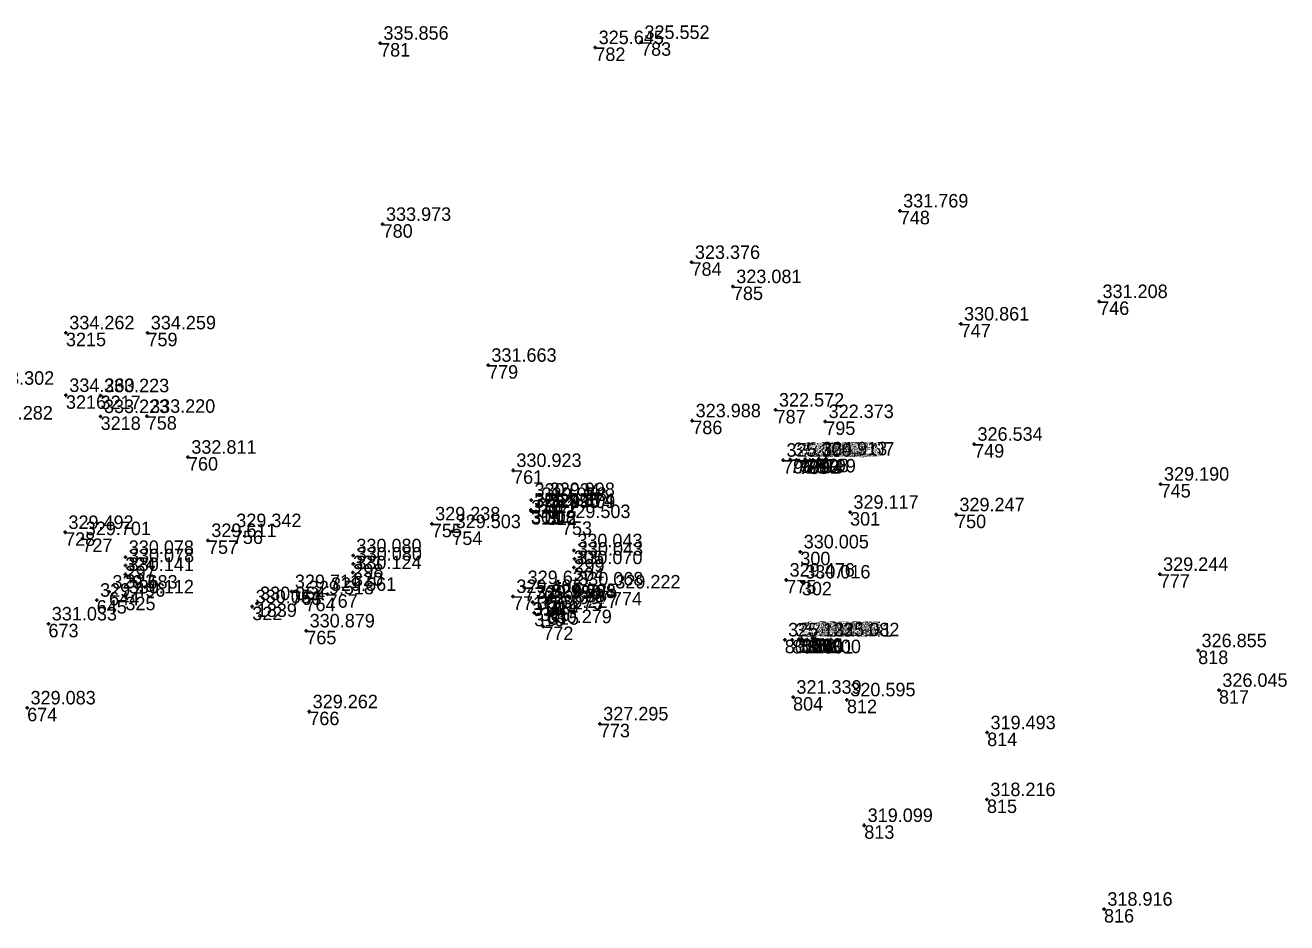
# Model space of a CAD drawing. Extents: x -829398 to -819400, y -1074439 to -1067977.
# Drawn here: x -824511.5 to -824399.2, y -1072412.8 to -1072332.9 of the extents above; entities that cross this region are included whole.
import ezdxf

# ---------------------------------------------------------------- set-up
doc = ezdxf.new("R2010")
doc.units = 0
for name, color, linetype in [('Vrstva 60', 7, 'Continuous'), ('Vrstva 61', 7, 'Continuous'), ('Čísla bodů_doměření_2012', 7, 'Continuous')]:
    doc.layers.add(name, color=color, linetype=linetype)

# ---------------------------------------------------------------- blocks, each defined once
blk = doc.blocks.new('BOD')
at = {"layer": 'Čísla bodů_doměření_2012'}
for p, q in [((-0.15, 0), (0.15, 0)), ((0, -0.15), (0, 0.15))]:
    blk.add_line(p, q, dxfattribs=at)

msp = doc.modelspace()

# ---------------------------------------------------------------- block references
at = {"layer": 'Vrstva 60'}
for p in [(-824479.933, -1072334.535), (-824460.777, -1072334.929), (-824456.704, -1072334.466), (-824433.677, -1072349.465), (-824479.706, -1072350.656), (-824452.213, -1072354.044), (-824448.53, -1072356.201), (-824415.935, -1072357.526), (-824428.259, -1072359.525), (-824507.891, -1072360.309), (-824500.638, -1072360.312), (-824470.324, -1072363.198), (-824507.89, -1072365.882), (-824504.805, -1072365.91), (-824444.732, -1072367.184), (-824504.805, -1072367.759), (-824500.702, -1072367.738), (-824452.146, -1072368.139), (-824440.312, -1072368.207), (-824427.062, -1072370.226), (-824497.031, -1072371.379), (-824444.066, -1072371.646), (-824443.438, -1072371.592), (-824442.883, -1072371.636), (-824442.653, -1072371.678), (-824442.638, -1072371.684), (-824442.107, -1072371.567), (-824441.669, -1072371.645), (-824441.659, -1072371.656), (-824441.409, -1072371.617), (-824440.889, -1072371.523), (-824440.262, -1072371.546), (-824468.099, -1072372.558), (-824410.462, -1072373.776), (-824466.482, -1072375.207), (-824465.136, -1072375.148), (-824466.507, -1072376.083), (-824466.498, -1072376.184), (-824465.863, -1072375.576), (-824465.195, -1072376.114), (-824465.101, -1072376.213), (-824438.103, -1072376.276), (-824475.329, -1072377.309), (-824463.747, -1072377.104), (-824428.669, -1072376.503), (-824507.969, -1072378.075), (-824506.428, -1072378.624), (-824493.032, -1072377.913), (-824473.506, -1072378.001), (-824495.251, -1072378.792), (-824462.677, -1072379.7), (-824442.53, -1072379.802), (-824502.6, -1072380.298), (-824482.34, -1072380.149), (-824482.313, -1072380.883), (-824462.627, -1072380.442), (-824502.605, -1072381.813), (-824502.582, -1072381.033), (-824482.346, -1072381.653), (-824462.676, -1072381.208), (-824410.543, -1072381.804), (-824467.1, -1072382.981), (-824462.599, -1072383.105), (-824443.784, -1072382.317), (-824442.393, -1072382.481), (-824505.152, -1072384.106), (-824504.055, -1072383.382), (-824502.6, -1072383.811), (-824487.815, -1072383.339), (-824486.576, -1072383.891), (-824484.601, -1072383.584), (-824468.103, -1072383.773), (-824466.368, -1072384.28), (-824466.343, -1072384.304), (-824465.049, -1072384.228), (-824464.946, -1072384.143), (-824459.297, -1072383.372), (-824491.304, -1072384.69), (-824490.91, -1072384.405), (-824466.21, -1072385.238), (-824465.679, -1072384.76), (-824464.906, -1072385.096), (-824509.449, -1072386.217), (-824465.408, -1072386.458), (-824486.5, -1072386.835), (-824443.919, -1072387.635), (-824443.263, -1072387.652), (-824442.667, -1072387.591), (-824442.421, -1072387.534), (-824442.418, -1072387.577), (-824441.908, -1072387.625), (-824441.445, -1072387.5), (-824441.418, -1072387.535), (-824441.201, -1072387.519), (-824440.486, -1072387.658), (-824439.815, -1072387.626), (-824407.119, -1072388.598), (-824405.269, -1072392.124), (-824443.177, -1072392.737), (-824438.38, -1072392.968), (-824511.342, -1072393.689), (-824486.232, -1072394.034), (-824460.371, -1072395.116), (-824425.902, -1072395.9), (-824425.919, -1072401.852), (-824436.836, -1072404.15), (-824415.502, -1072411.603)]:
    msp.add_blockref('BOD', p, dxfattribs=at)

# ---------------------------------------------------------------- texts
for s, p in [('781', (-824479.933, -1072335.735)), ('783', (-824456.704, -1072335.666)), ('782', (-824460.777, -1072336.129)), ('748', (-824433.677, -1072350.665)), ('780', (-824479.706, -1072351.856)), ('784', (-824452.213, -1072355.244)), ('785', (-824448.53, -1072357.401)), ('746', (-824415.935, -1072358.726)), ('3215', (-824507.891, -1072361.509)), ('759', (-824500.638, -1072361.512)), ('747', (-824428.259, -1072360.725)), ('779', (-824470.324, -1072364.398)), ('3216', (-824507.89, -1072367.082)), ('3217', (-824504.805, -1072367.11)), ('787', (-824444.732, -1072368.384)), ('3218', (-824504.805, -1072368.959)), ('758', (-824500.702, -1072368.938)), ('786', (-824452.146, -1072369.339)), ('795', (-824440.312, -1072369.407)), ('749', (-824427.062, -1072371.426)), ('760', (-824497.031, -1072372.579)), ('796', (-824444.066, -1072372.846)), ('797', (-824443.438, -1072372.792)), ('788', (-824442.883, -1072372.836)), ('790', (-824442.653, -1072372.878)), ('789', (-824442.638, -1072372.884)), ('791', (-824442.107, -1072372.767)), ('792', (-824441.669, -1072372.845)), ('793', (-824441.659, -1072372.856)), ('794', (-824441.409, -1072372.817)), ('798', (-824440.889, -1072372.723)), ('799', (-824440.262, -1072372.746)), ('761', (-824468.099, -1072373.758)), ('745', (-824410.462, -1072374.976)), ('310', (-824466.482, -1072376.407)), ('311', (-824465.136, -1072376.348)), ('309', (-824466.507, -1072377.283)), ('313', (-824466.498, -1072377.384)), ('307', (-824465.863, -1072376.776)), ('308', (-824465.195, -1072377.314)), ('312', (-824465.101, -1072377.413)), ('301', (-824438.103, -1072377.476)), ('755', (-824475.329, -1072378.509)), ('753', (-824463.747, -1072378.304)), ('750', (-824428.669, -1072377.703)), ('728', (-824507.969, -1072379.275)), ('756', (-824493.032, -1072379.113)), ('754', (-824473.506, -1072379.201)), ('727', (-824506.428, -1072379.824)), ('757', (-824495.251, -1072379.992)), ('305', (-824462.677, -1072380.9)), ('324', (-824502.6, -1072381.498)), ('321', (-824482.34, -1072381.349)), ('299', (-824462.627, -1072381.642)), ('300', (-824442.53, -1072381.002)), ('323', (-824502.605, -1072383.013)), ('297', (-824502.582, -1072382.233)), ('320', (-824482.346, -1072382.853)), ('298', (-824482.313, -1072382.083)), ('304', (-824462.676, -1072382.408)), ('777', (-824410.543, -1072383.004)), ('770', (-824467.1, -1072384.181)), ('775', (-824443.784, -1072383.517)), ('302', (-824442.393, -1072383.681)), ('645', (-824505.152, -1072385.306)), ('644', (-824504.055, -1072384.582)), ('325', (-824502.6, -1072385.011)), ('763', (-824487.815, -1072384.539)), ('764', (-824486.576, -1072385.091)), ('767', (-824484.601, -1072384.784)), ('771', (-824468.103, -1072384.973)), ('319', (-824464.946, -1072385.343)), ('303', (-824462.599, -1072384.305)), ('774', (-824459.297, -1072384.572)), ('322', (-824491.304, -1072385.89)), ('1839', (-824490.91, -1072385.605)), ('318', (-824466.368, -1072385.48)), ('317', (-824466.343, -1072385.504)), ('316', (-824466.21, -1072386.438)), ('306', (-824465.679, -1072385.96)), ('314', (-824465.049, -1072385.428)), ('315', (-824464.906, -1072386.296)), ('673', (-824509.449, -1072387.417)), ('772', (-824465.408, -1072387.658)), ('765', (-824486.5, -1072388.035)), ('806', (-824442.421, -1072388.734)), ('807', (-824442.418, -1072388.777)), ('810', (-824441.445, -1072388.7)), ('809', (-824441.418, -1072388.735)), ('811', (-824441.201, -1072388.719)), ('803', (-824443.919, -1072388.835)), ('802', (-824443.263, -1072388.852)), ('805', (-824442.667, -1072388.791)), ('808', (-824441.908, -1072388.825)), ('801', (-824440.486, -1072388.858)), ('800', (-824439.815, -1072388.826)), ('818', (-824407.119, -1072389.798)), ('804', (-824443.177, -1072393.937)), ('812', (-824438.38, -1072394.168)), ('817', (-824405.269, -1072393.324)), ('674', (-824511.342, -1072394.889)), ('766', (-824486.232, -1072395.234)), ('773', (-824460.371, -1072396.316)), ('814', (-824425.902, -1072397.1)), ('815', (-824425.919, -1072403.052)), ('813', (-824436.836, -1072405.35)), ('816', (-824415.502, -1072412.803))]:
    msp.add_text(s, height=1.2, dxfattribs=at).set_placement(p)
at = {"layer": 'Vrstva 61'}
for s, p in [('335.856', (-824479.633, -1072334.235)), ('325.645', (-824460.477, -1072334.629)), ('325.552', (-824456.404, -1072334.166)), ('331.769', (-824433.377, -1072349.165)), ('333.973', (-824479.406, -1072350.356)), ('323.376', (-824451.913, -1072353.744)), ('323.081', (-824448.23, -1072355.901)), ('331.208', (-824415.635, -1072357.226)), ('330.861', (-824427.959, -1072359.225)), ('334.262', (-824507.591, -1072360.009)), ('334.259', (-824500.338, -1072360.012)), ('331.663', (-824470.024, -1072362.898)), ('333.302', (-824514.736, -1072364.941)), ('334.260', (-824507.59, -1072365.582)), ('333.223', (-824504.505, -1072365.61)), ('333.220', (-824500.402, -1072367.438)), ('322.572', (-824444.432, -1072366.884)), ('333.282', (-824514.859, -1072368.036)), ('333.223', (-824504.505, -1072367.459)), ('323.988', (-824451.846, -1072367.839)), ('322.373', (-824440.012, -1072367.907)), ('326.534', (-824426.762, -1072369.926)), ('332.811', (-824496.731, -1072371.079)), ('325.300', (-824443.766, -1072371.346)), ('324.895', (-824443.138, -1072371.292)), ('321.066', (-824442.583, -1072371.336)), ('323.511', (-824442.353, -1072371.378)), ('321.078', (-824442.338, -1072371.384)), ('324.035', (-824441.807, -1072371.267)), ('323.562', (-824441.369, -1072371.345)), ('321.113', (-824441.359, -1072371.356)), ('321.116', (-824441.109, -1072371.317)), ('324.913', (-824440.589, -1072371.223)), ('325.307', (-824439.962, -1072371.246)), ('330.923', (-824467.799, -1072372.258)), ('329.190', (-824410.162, -1072373.476)), ('330.034', (-824466.182, -1072374.907)), ('329.958', (-824465.563, -1072375.276)), ('329.998', (-824464.836, -1072374.848)), ('329.925', (-824466.207, -1072375.783)), ('329.496', (-824466.198, -1072375.884)), ('329.874', (-824464.895, -1072375.814)), ('329.409', (-824464.801, -1072375.913)), ('329.117', (-824437.803, -1072375.976)), ('329.247', (-824428.369, -1072376.203)), ('329.238', (-824475.029, -1072377.009)), ('329.503', (-824463.447, -1072376.804)), ('329.492', (-824507.669, -1072377.775)), ('329.701', (-824506.128, -1072378.324)), ('329.611', (-824494.951, -1072378.492)), ('329.342', (-824492.732, -1072377.613)), ('329.503', (-824473.206, -1072377.701)), ('330.043', (-824462.377, -1072379.4)), ('330.005', (-824442.23, -1072379.502)), ('330.078', (-824502.3, -1072379.998)), ('330.078', (-824502.282, -1072380.733)), ('330.080', (-824482.04, -1072379.849)), ('330.080', (-824482.013, -1072380.583)), ('330.070', (-824462.376, -1072380.908)), ('330.043', (-824462.327, -1072380.142)), ('330.141', (-824502.305, -1072381.513)), ('330.124', (-824482.046, -1072381.353)), ('329.476', (-824443.484, -1072382.017)), ('329.244', (-824410.243, -1072381.504)), ('329.683', (-824503.755, -1072383.082)), ('329.711', (-824487.515, -1072383.039)), ('329.627', (-824466.8, -1072382.681)), ('330.068', (-824462.299, -1072382.805)), ('329.222', (-824458.997, -1072383.072)), ('330.016', (-824442.093, -1072382.181)), ('329.496', (-824504.852, -1072383.806)), ('330.112', (-824502.3, -1072383.511)), ('330.064', (-824490.61, -1072384.105)), ('329.518', (-824486.276, -1072383.591)), ('329.561', (-824484.301, -1072383.284)), ('329.407', (-824467.803, -1072383.473)), ('329.790', (-824466.068, -1072383.98)), ('329.954', (-824466.043, -1072384.004)), ('329.998', (-824464.749, -1072383.928)), ('329.725', (-824464.646, -1072383.843)), ('330.054', (-824491.004, -1072384.39)), ('330.273', (-824465.91, -1072384.938)), ('330.037', (-824465.379, -1072384.46)), ('330.227', (-824464.606, -1072384.796)), ('331.033', (-824509.149, -1072385.917)), ('330.879', (-824486.2, -1072386.535)), ('330.279', (-824465.108, -1072386.158)), ('325.123', (-824443.619, -1072387.335)), ('324.764', (-824442.963, -1072387.352)), ('320.596', (-824442.367, -1072387.291)), ('320.529', (-824442.121, -1072387.234)), ('323.537', (-824442.118, -1072387.277)), ('324.028', (-824441.608, -1072387.325)), ('320.568', (-824441.145, -1072387.2)), ('323.542', (-824441.118, -1072387.235)), ('320.651', (-824440.901, -1072387.219)), ('324.741', (-824440.186, -1072387.358)), ('325.082', (-824439.515, -1072387.326)), ('326.855', (-824406.819, -1072388.298)), ('326.045', (-824404.969, -1072391.824)), ('321.339', (-824442.877, -1072392.437)), ('320.595', (-824438.08, -1072392.668)), ('329.083', (-824511.042, -1072393.389)), ('329.262', (-824485.932, -1072393.734)), ('327.295', (-824460.071, -1072394.816)), ('319.493', (-824425.602, -1072395.6)), ('318.216', (-824425.619, -1072401.552)), ('319.099', (-824436.536, -1072403.85)), ('318.916', (-824415.202, -1072411.303))]:
    msp.add_text(s, height=1.2, dxfattribs=at).set_placement(p)

doc.saveas('drawing.dxf')
